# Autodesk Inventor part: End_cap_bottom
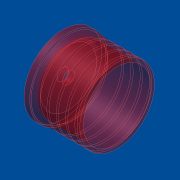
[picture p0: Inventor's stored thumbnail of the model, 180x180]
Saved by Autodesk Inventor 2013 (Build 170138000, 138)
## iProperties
Shininess: 20.0
Length Units: 11269
Angle Units: 11279
Time Units: 11290
Mass Units: 11283
Length Display Precision: 3
Angle Display Precision: 2
Created: 2001-04
Part Number: End_cap_bottom
Material: Standard
Document SubType Name: Modellieren
Designer: dl
Density: 1 g/cm^3
Density: 0.0
Volumn: 0.0
Area: 0.0
PropertySet Name: Model Information
Control State: 0
Master: False
Checked Out: False
Author: dl
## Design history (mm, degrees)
body "Solid1"
revolve "Revolution1" stored, may be unused: angle "d5" = 90 deg
revolve "Revolution2" stored, may be unused: angle "d9" = 90 deg
pattern_linear "Rectangular Pattern1" dims "d12" = 5
sketch "Sketch3"
  geometry: C1 r 20 at (0, 0) reference; 1 further point
  constraints: 1 coincident
hole "Hole1" sketch "Sketch3" diameter "d13" = 6.4; stored, may be unused: countersink angle "d17" = 60 deg, drill point angle "d19" = 118 deg; dims "d14" = 6, "d15" = 36, "d16" = 26, "d18" = 8
fillet "Fillet1" dims "d20" = 3
sketch "Sketch1"
  geometry: L1 (-9, 0)-(-9, 20.8); L2 (-9, 20.8)-(-6, 20.8); L3 (-6, 20.8)-(-6, 20); L4 (-6, 20)-(20, 20); L5 (20, 20)-(20, 0); L6 (20, 0)-(-9, 0)
  constraints: 12 end point, 4 parallel, 1 perpendicular, 1 vertical
  dimensions: "d1" = 26 distance of L3.end L4.end; "d2" = 29 distance of L5.end L1.start; "d3" = 20 distance of L4.end L5.end; "d4" = 20.8 distance of L1.start L1.end
sketch "Sketch2"
  geometry: L1 (-9, -20.8)-(-9, 20.8) reference; L2 (-9, 0)-(27.932, 0); L3 (20, -20)-(20, 20) reference; C1 r 1 at (18, 20.8)
  constraints: 2 end point, 1 centre point, 1 midpoint, 1 perpendicular
  dimensions: "d6" = 2 diameter of C1; "d7" = 20.8 distance from line of C1.centre L2; "d8" = 2 distance from line of L3 C1.centre
